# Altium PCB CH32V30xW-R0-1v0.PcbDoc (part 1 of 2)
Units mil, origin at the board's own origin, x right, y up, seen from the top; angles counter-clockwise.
Board outline 3543.31 x 3070.87 mil, 2 copper layers (Top Layer, Bottom Layer); 66 components, 88 nets, 346 pads, 719 vias.
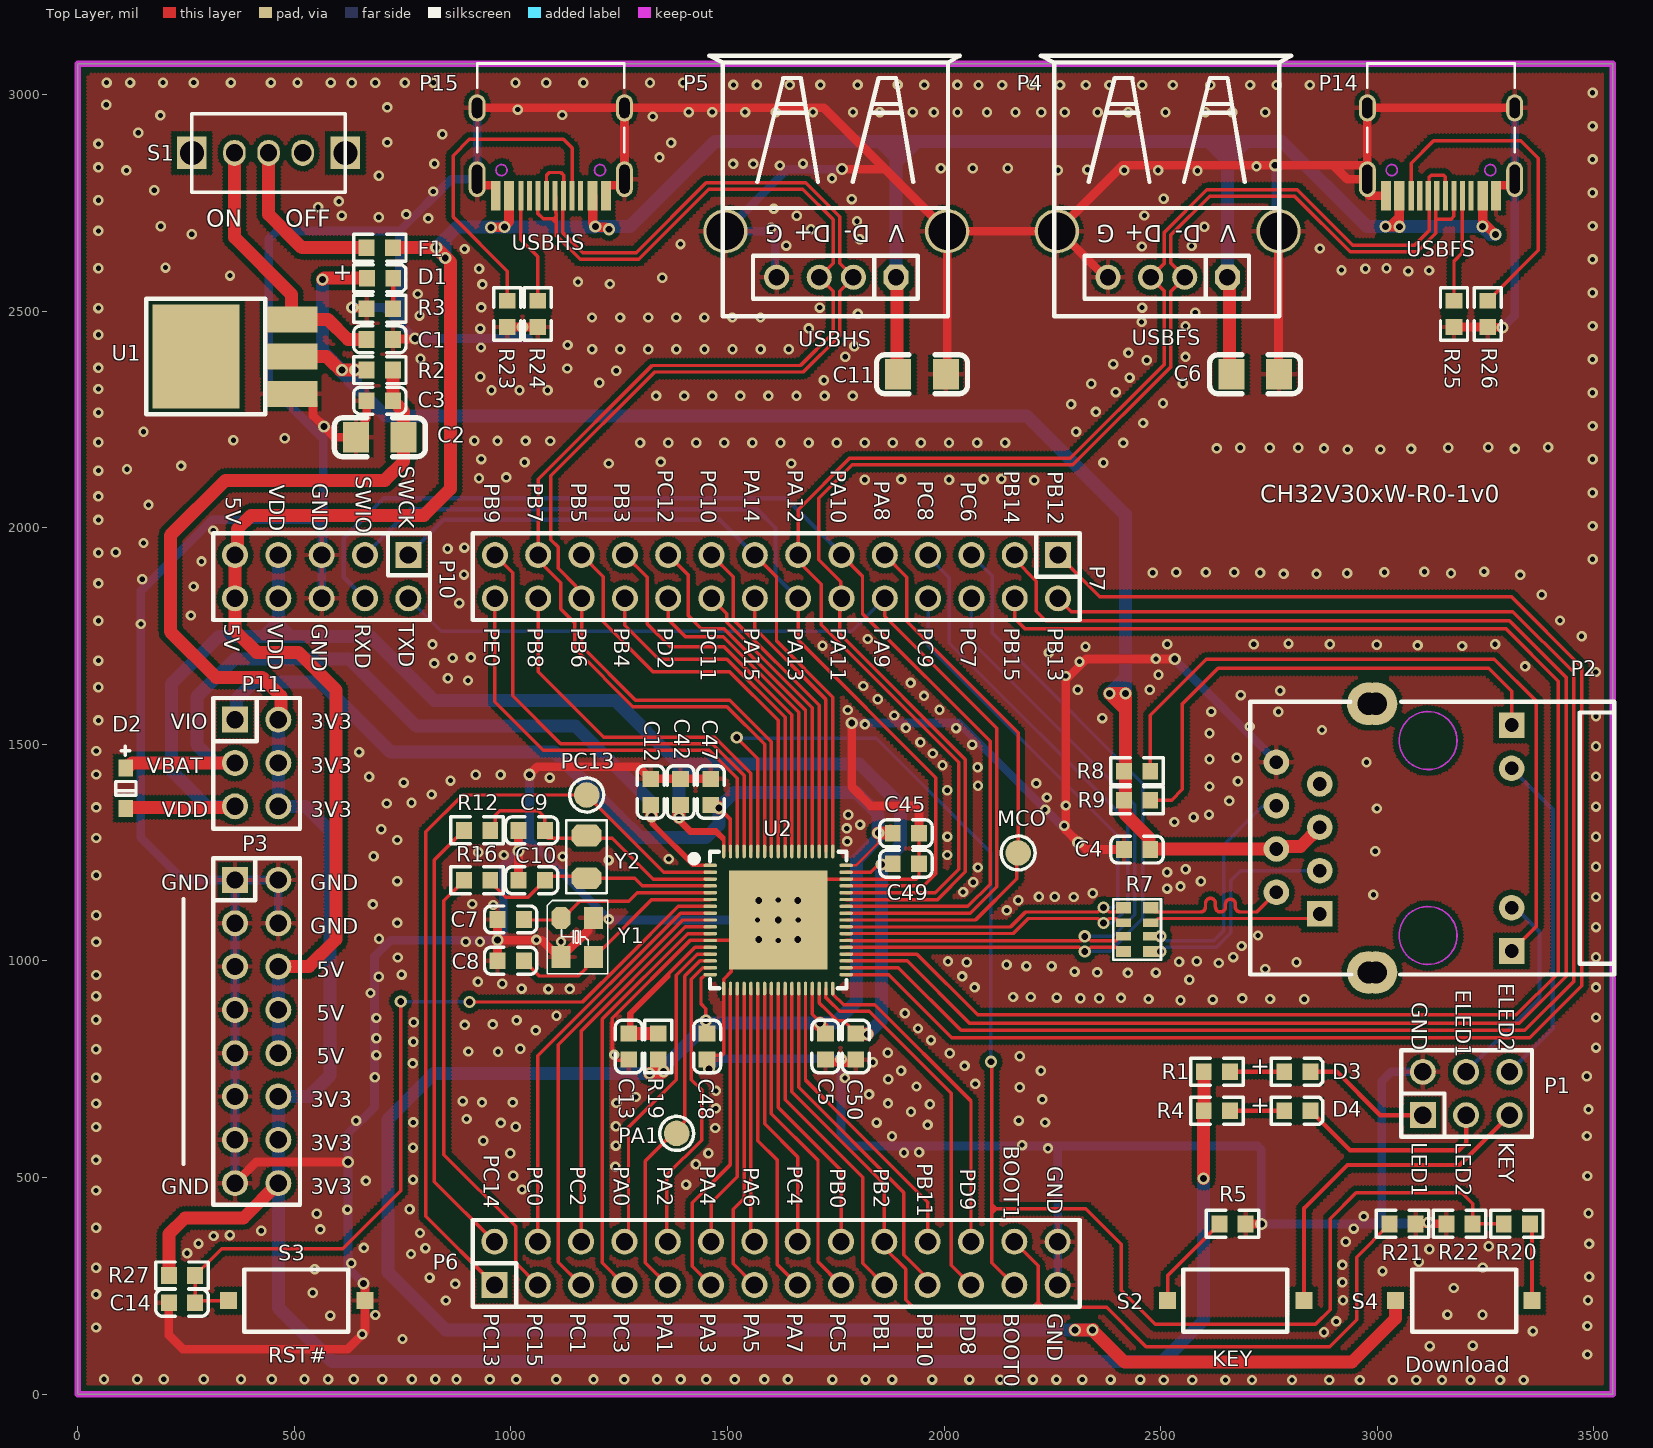
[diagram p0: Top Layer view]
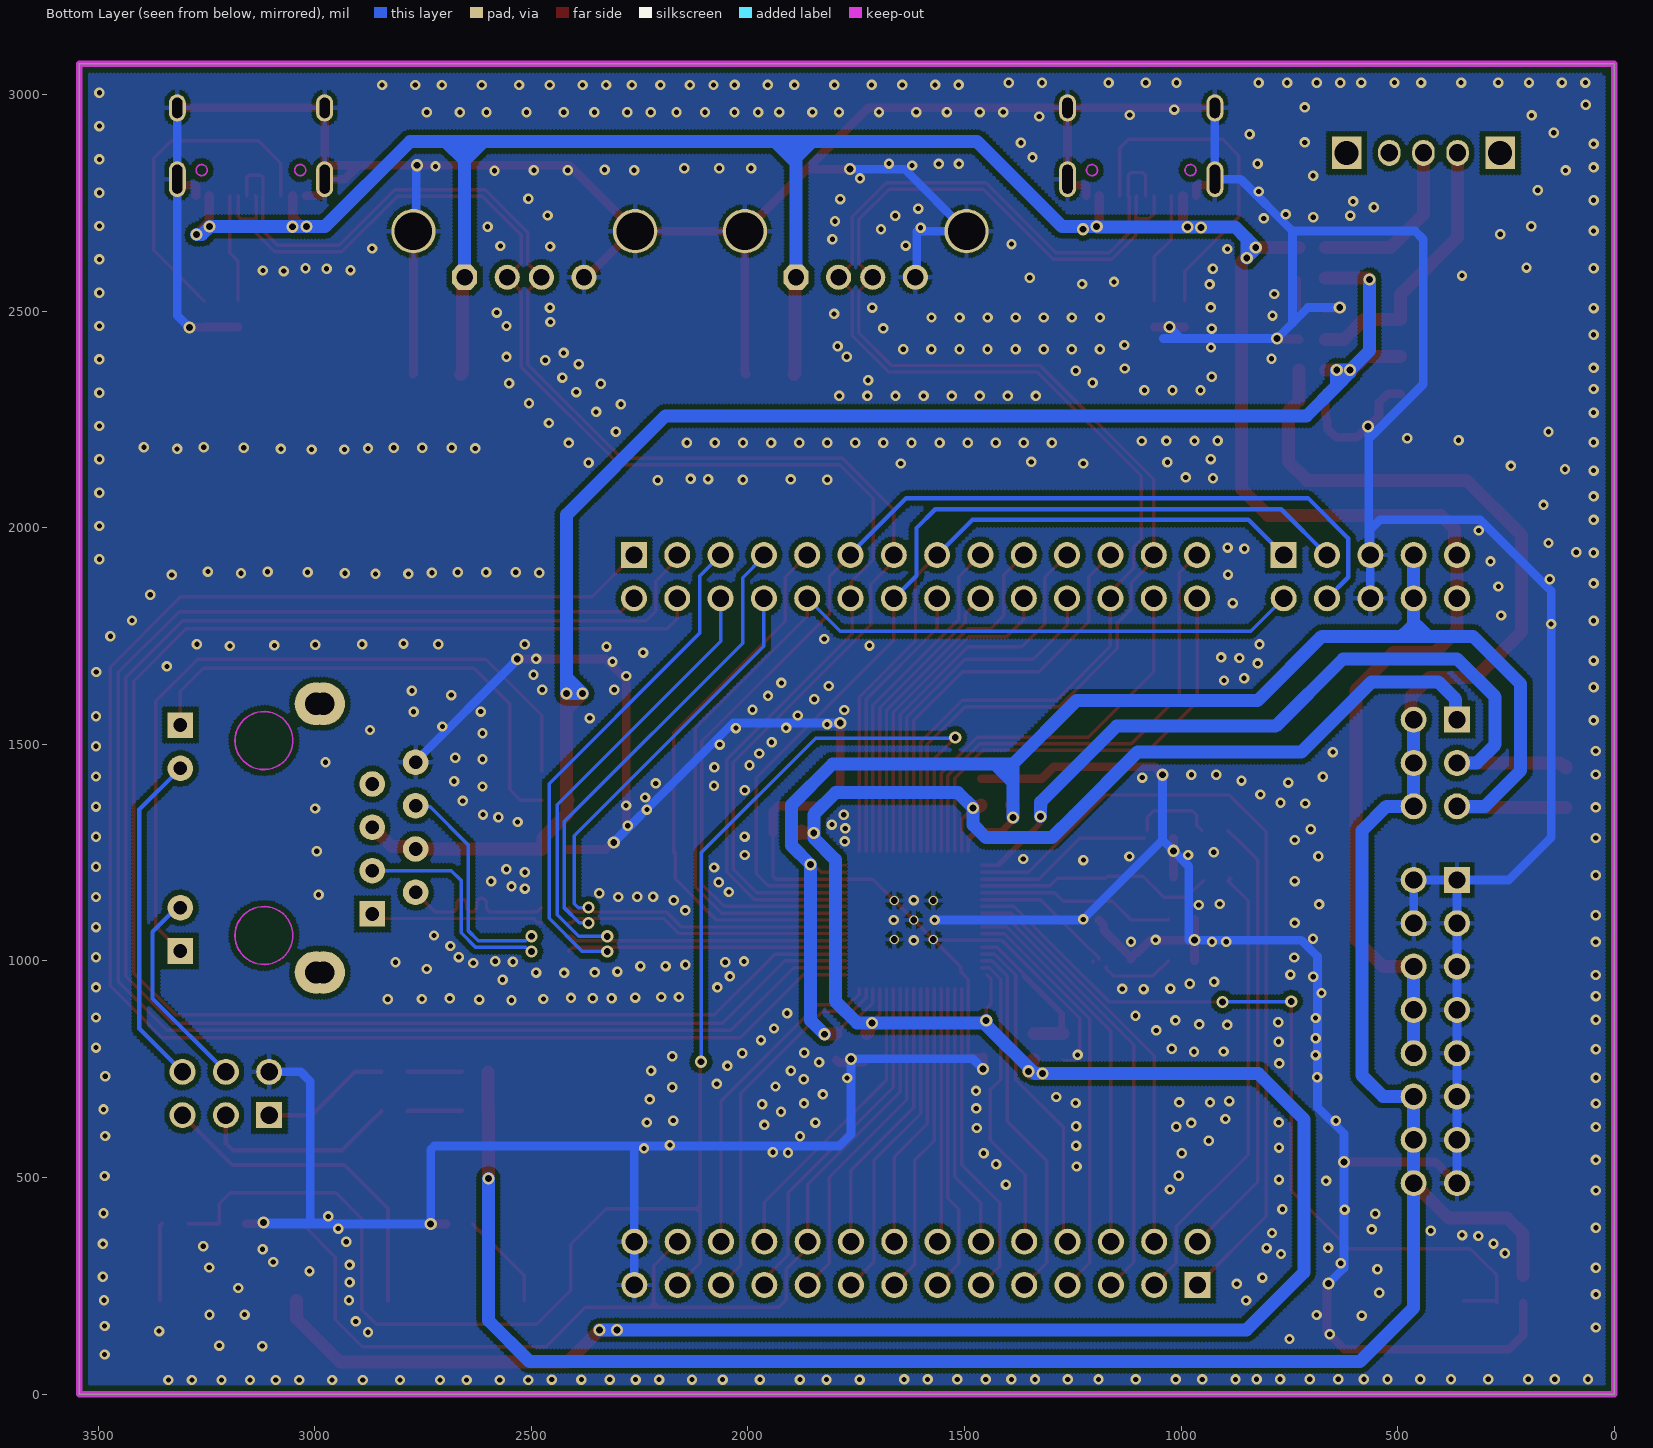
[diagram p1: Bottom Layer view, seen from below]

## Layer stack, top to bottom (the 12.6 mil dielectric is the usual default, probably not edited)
Top Solder: solder mask 0.4, Solder Resist, Dk 3.5
Top Layer: signal copper 1.4
Dielectric 1: dielectric 12.6, FR-4, Dk 4.8
Bottom Layer: signal copper 1.4
Bottom Solder: solder mask 0.4, Solder Resist, Dk 3.5

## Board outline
0,0 3543.31,0 3543.31,3070.87 0,3070.87

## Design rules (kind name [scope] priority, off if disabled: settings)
Clearance Clearance_1 [InPolygon] p1: gap=12 ignorepadtopadclearanceinfootprint=FALSE
Clearance [All] p2: gap=7 ignorepadtopadclearanceinfootprint=FALSE
ComponentClearance [All] p1 off: gap=10 collisioncheckmode=3 verticalgap=10 showdistances=FALSE
DiffPairsRouting [All] p1: maxlimit=10 minlimit=7 mostfreqgap=8 toplayer_minwidth=7 toplayer_maxwidth=15 toplayer_prefwidth=8 bottomlayer_minwidth=7 bottomlayer_maxwidth=15 bottomlayer_prefwidth=8 maxuncoupledlength=500
MinimumSolderMaskSliver [All] p1 off: minsoldermaskwidth=10
PolygonConnect PolygonConnect_1 [IsVia] p1: connectstyle=Direct reliefconductorwidth=10 reliefentries=4 polygonreliefangle="90 Angle" airgapwidth=10
PolygonConnect [All] p2: connectstyle=Relief reliefconductorwidth=10 reliefentries=4 polygonreliefangle="90 Angle" airgapwidth=10
RoutingVias [All] p1: holewidth=16 width=28 viastyle="Through Hole" minholewidth=12 minwidth=24 maxholewidth=28 maxwidth=50
SilkToSilkClearance [All] p1 off: silktosilkclearance=10
SilkToSolderMaskClearance [IsPad] p1 off: minsilkscreentomaskgap=10 clearancetoexposedcopper=TRUE
SolderMaskExpansion [All] p1: expansion=4 istentingtop=FALSE
Width [All] p1: maxlimit=100 minlimit=6 preferedwidth=10
25 further rules are at their usual default settings.

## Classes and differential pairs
differential pair NewDifferentialPair6: +PB7 -PB6
differential pair NewDifferentialPair5: +PA12 -PA11
differential pair NewDifferentialPair4: +ERXN1 -ERXP1
differential pair NewDifferentialPair3: +ETXN1 -ETXP1
differential pair NewDifferentialPair2: +ERXN -ERXP
differential pair NewDifferentialPair1: +ETXN -ETXP

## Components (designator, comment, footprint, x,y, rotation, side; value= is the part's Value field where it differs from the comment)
C1 "0.1uF" 0603_C 667.02,2434.74 r0 top
C2 "10uF" 3216_C 752.33,2208.79 r0 top
C3 "0.1uF" 0603_C 727.65,2293.47 r180 top
C4 "1uF" 0603_C 2415.29,1257.18 r0 top
C5 "0.1uF" 0603_C 1726.06,772.13 r90 top
C6 "10uF" 3216_C 2663,2354.26 r180 top
C7 "22pF" 0603_C 969.2,1095.74 r0 top
C8 "22pF" 0603_C 969.2,1000.46 r0 top
C9 "12pF" 0603_C 1017.69,1301.31 r0 top
C10 "12pF" 0603_C 1017.69,1186.19 r0 top
C11 "10uF" 3216_C 1894,2354.26 r180 top
C12 "0.1uF" 0603_C 1322.64,1420.35 r270 top
C13 "0.1uF" 0603_C 1272.27,832.76 r270 top
C14 "0.1uF" 0603_C 210.37,211 r0 top
C42 "0.1uF" 0603_C 1391.63,1420.35 r270 top
C45 "0.1uF" 0603_C 1881.48,1294.49 r0 top
C47 "0.1uF" 0603_C 1461.63,1359.72 r90 top
C48 "0.1uF" 0603_C 1452.92,832.76 r270 top
C49 "0.1uF" 0603_C 1942.11,1224.49 r180 top
C50 "0.1uF" 0603_C 1796.06,832.76 r270 top
D1 "RED" 0603+ 667.71,2576.01 r0 top
D2 "B0520WS" SOD-323 111,1444.91 r270 top
D3 "BLUE" 0603+ 2785.11,743.99 r0 top
D4 "RED" 0603+ 2785.11,653.99 r0 top
F1 "500mA" 0603 727.65,2646.64 r180 top
MCO "Testpoint" TESTPOINT1 2170.88,1249.31 r0 top
P1 "IO" IDC6-2.54mm 3105.11,643.99 r0 top
P2 "HR911105A" HR911105A 2867.11,1108.49 r90 top
P3 "Ppin" IDC16-2.54mm 363.11,1186.99 r0 top
P4 "USBFS" USBAF 2654,2578.25 r180 top
P5 "USBHS" USBAF 1889,2578.25 r180 top
P6 "HEADER 14x2" IDC28-2.54MM 962.11,251.99 r90 top
P7 "HEADER 14x2" IDC28-2.54MM 2263.11,1936.99 r270 top
P10 "LINK" IDC10-2.54mm 363.11,1936.99 r270 top
P11 "Psel" IDC6-2.54mm 363.11,1556.99 r270 top
P14 "USBFS" TYPE-C-Receptacle-2.0 3147.18,2766.56 r180 top
P15 "USBHS" TYPE-C-Receptacle-2.0 1092.03,2766.56 r180 top
PA1 "Testpoint" TESTPOINT1 1382.65,601.9 r0 top
PC13 "Testpoint" TESTPOINT1 1174.94,1383.09 r0 top
R1 "1K" 0603 2599.48,743.99 r0 top
R2 "0R" 0603 727.65,2364.1 r180 top
R3 "1K" 0603 727.65,2505.37 r180 top
R4 "1K" 0603 2599.48,653.99 r0 top
R5 "10K" 0603 2696,392.95 r180 top
R7 "0Ω" 8P4R-0603 2445.6,1072.43 r270 top
R8 "1K" 0603 2415.29,1437.8 r0 top
R9 "1K" 0603 2415.29,1371.1 r0 top
R12 "NC(0R)" 0603 891.69,1301.31 r0 top
R16 "NC(0R)" 0603 891.69,1186.19 r0 top
R19 "0R" 0603 1339.92,772.13 r90 top
R20 "1K" 0603 3291.86,392.95 r0 top
R21 "10K" 0603 3028,392.95 r0 top
R22 "10K" 0603 3220,392.95 r180 top
R23 "5.1K" 0603 991.75,2523.92 r270 top
R24 "5.1K" 0603 1062.11,2523.92 r270 top
R25 "5.1K" 0603 3177.11,2523.88 r270 top
R26 "5.1K" 0603 3255.21,2523.88 r270 top
R27 "10K" 0603 271,274 r180 top
S1 "SW SPDT" KEY2 440.58,2865.37 r0 top
S2 "KEY" SMD_6.1x3.65x2.5mm-KEY 2830.75,215.99 r180 top
S3 "RST#" SMD_6.1x3.65x2.5mm-KEY 663.07,215.99 r180 top
S4 "Download" SMD_6.1x3.65x2.5mm-KEY 3042,215.99 r0 top
U1 "1117-3.3V" SOT-223 493.11,2309.25 r90 top
U2 "CH32V307W" QFN68_8x8 1617.11,1094.49 r270 top
Y1 "8MHz" XT3225 1115.58,1099.48 r270 top
Y2 "32768Hz" FC-135 1174.48,1289.69 r270 top

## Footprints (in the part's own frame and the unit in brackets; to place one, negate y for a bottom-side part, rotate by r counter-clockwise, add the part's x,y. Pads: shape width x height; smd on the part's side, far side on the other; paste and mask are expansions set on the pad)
8P4R-0603 [mm]
  rect 0.65x0.9 smd: 1(-1.28,-0.8) 4(1.28,-0.8) 5(1.28,0.8) 8(-1.28,0.8)
  rect 0.5x0.9 smd: 2(-0.4,-0.8) 3(0.4,-0.8) 6(0.4,0.8) 7(-0.4,0.8)
  silkscreen extent -1.78,-1.4 1.78,1.4, body extent -1.6,-0.8 1.6,0.8, height 0.6
0603 [mm]
  rect 0.93x0.98 smd: 1(0,0) 2(1.54,0)
  silkscreen extent -0.76,-0.79 2.3,0.79
0603+ [mm]
  rect 0.93x0.98 smd: 1(0,0) 2(1.54,0)
  silkscreen extent -0.76,-0.79 2.27,0.79
0603_C [mm]
  rect 0.93x0.98 smd: 1(0,0) 2(1.54,0)
  silkscreen extent -0.76,-0.79 2.31,0.79
3216_C [mil]
  rect 60x70 smd: 1(0,0) 2(-110,0)
  silkscreen extent -160,-45 50,45
FC-135 [mil]
  oct 50x70 smd: 1(0,0) 2(98.43,0)
  silkscreen extent -35,-47 133,47
HR911105A [mm]
  rect 1.5x1.5 hole 0.8: 1(0,0) 9(-2.175,-11.252) 12(11.075,-11.252)
  round 1.5 hole 0.8: 2(1.27,2.54) 3(2.54,0) 4(3.81,2.54) 5(5.08,0) 6(6.35,2.54) 7(7.62,0) 8(8.89,2.54) 10(0.365,-11.252) 11(8.535,-11.252)
  round 2.5 hole 1.3: ""(-3.43,-2.852) ""(-3.43,-3.3) ""(12.32,-3.3) ""(12.32,-2.852)
  Keep-Out Layer circle w0.1: c10.165,-6.352 r1.7
  Keep-Out Layer circle w0.1: c-1.265,-6.352 r1.7
  silkscreen extent -3.55,-17.27 12.45,4.06
IDC6-2.54mm [mil]
  rect 60x60 hole 40: 1(0,0)
  round 60 hole 40: 2(0,100) 3(100,0) 4(100,100) 5(200,0) 6(200,100)
  silkscreen extent -50,-50 252,150
IDC10-2.54mm [mil]
  rect 60x60 hole 40: 1(0,400)
  round 60 hole 40: 2(100,400) 3(0,300) 4(100,300) 5(0,200) 6(100,200) 7(0,100) 8(100,100) 9(0,0) 10(100,0)
  silkscreen extent -50,-50 150,450
IDC16-2.54mm [mil]
  rect 60x60 hole 40: 1(0,0)
  round 60 hole 40: 2(100,0) 3(0,-100) 4(100,-100) 5(0,-200) 6(100,-200) 7(0,-300) 8(100,-300) 9(0,-400) 10(100,-400) 11(0,-500) 12(100,-500) 13(0,-600) 14(100,-600) 15(0,-700) 16(100,-700)
  silkscreen extent -50,-750 150,50
IDC28-2.54MM [mil]
  rect 60x60 hole 40: 1(0,0)
  round 60 hole 40: 2(100,0) 3(0,-100) 4(100,-100) 5(0,-200) 6(100,-200) 7(0,-300) 8(100,-300) 9(0,-400) 10(100,-400) 11(0,-500) 12(100,-500) 13(0,-600) 14(100,-600) 15(0,-700) 16(100,-700) 17(0,-800) 18(100,-800) 19(0,-900) 20(100,-900) 21(0,-1000) 22(100,-1000) 23(0,-1100) 24(100,-1100) 25(0,-1200) 26(100,-1200) 27(0,-1300) 28(100,-1300)
  silkscreen extent -50,-1351 150,50
KEY2 [mm]
  rect 1.75x1.9 hole 1.4: 0(-4.5,0) 0(4.5,0)
  oval 1.321x1.524 hole 1.016: 1(0,0) 2(-2,0) 3(2,0)
  silkscreen extent -4.51,-2.31 4.5,2.29
QFN68_8x8 [mm]
  round 0.559 hole 0.406: 0(-1.143,1.143) 0(-1.143,-1.143) 0(0,0) 0(1.143,1.143) 0(1.143,-1.143)
  rect 5.8x5.8 smd: 0(0,0)
  oval 0.2x0.8 smd: 1(-3.2,-3.982) 2(-2.8,-3.982) 3(-2.4,-3.982) 4(-2,-3.982) 5(-1.6,-3.982) 6(-1.2,-3.982) 7(-0.8,-3.982) 8(-0.4,-3.982) 9(0,-3.982) 10(0.4,-3.982) 11(0.8,-3.982) 12(1.2,-3.982) 13(1.6,-3.982) 14(2,-3.982) 15(2.4,-3.982) 16(2.8,-3.982) 17(3.2,-3.982) 35(3.2,3.982) 36(2.8,3.982) 37(2.4,3.982) 38(2,3.982) 39(1.6,3.982) 40(1.2,3.982) 41(0.8,3.982) 42(0.4,3.982) 43(0,3.982) 44(-0.4,3.982) 45(-0.8,3.982) 46(-1.2,3.982) 47(-1.6,3.982) 48(-2,3.982) 49(-2.4,3.982) 50(-2.8,3.982) 51(-3.2,3.982)
  oval 0.8x0.2 smd: 18(4.018,-3.2) 19(4.018,-2.8) 20(4.018,-2.4) 21(4.018,-2) 22(4.018,-1.6) 23(4.018,-1.2) 24(4.018,-0.8) 25(4.018,-0.4) 26(4.018,0) 27(4.018,0.4) 28(4.018,0.8) 29(4.018,1.2) 30(4.018,1.6) 31(4.018,2) 32(4.018,2.4) 33(4.018,2.8) 34(4.018,3.2) 52(-4.018,3.2) 53(-4.018,2.8) 54(-4.018,2.4) 55(-4.018,2) 56(-4.018,1.6) 57(-4.018,1.2) 58(-4.018,0.8) 59(-4.018,0.4) 60(-4.018,0) 61(-4.018,-0.4) 62(-4.018,-0.8) 63(-4.018,-1.2) 64(-4.018,-1.6) 65(-4.018,-2) 66(-4.018,-2.4) 67(-4.018,-2.8) 68(-4.018,-3.2)
  silkscreen extent -4,-5.13 4,4
SMD_6.1x3.65x2.5mm-KEY [mm]
  rect 1x1 smd: 1(0,0) 2(8,0)
  silkscreen extent 0.98,-1.83 7.08,1.83
SOD-323 [mm]
  rect 1x0.83 smd: 1(0,0) 2(2.36,0)
  silkscreen extent -1.28,-0.6 1.58,0.6
SOT-223 [mil]
  rect 60x120 smd: 1(0,0) 2(86,0) 3(172,0)
  rect 240x200 smd: ""(86,220)
  silkscreen extent -47,60 219,335
TESTPOINT1 [mm]
  round 1.5 smd: 1(0,0)
  silkscreen extent -1,-1 1,1
TYPE-C-Receptacle-2.0 [mm]
  oval 1x2.1 hole 0.6 slot 1.7 at 90 deg: 0(-4.32,-0.97) 0(4.32,-0.97)
  oval 1x1.6 hole 0.6 slot 1.2 at 90 deg: 0(-4.32,-5.15) 0(4.32,-5.15)
  rect 0.584x1.75 smd: A1(-3.225,0) B1(3.225,0)
  rect 0.6x1.75 smd: A4(-2.45,0) B4(2.45,0)
  rect 0.3x1.75 smd: A5(-1.25,0) A6(-0.25,0) A7(0.25,0) A8(1.25,0) B5(1.75,0) B6(0.75,0) B7(-0.75,0) B8(-1.75,0)
  Keep-Out Layer circle w0.1: c2.89,-1.5 r0.325
  Keep-Out Layer circle w0.1: c-2.89,-1.5 r0.325
  silkscreen extent -4.32,-7.75 4.32,-2.55
USBAF [mm]
  round 2.6 hole 2.2: 0(-3,-2.7) 0(10,-2.7)
  oct 1.473x1.473 hole 0.965: 1(0,0)
  round 1.473 hole 0.965: 2(2.5,0) 3(4.5,0) 4(7,0)
  silkscreen extent -3.75,-12.99 10.95,2.29
XT3225 [mm]
  oct 1.3x1.1 smd: 1(0,0)
  rect 1.3x1.1 smd: 2(2.3,0) 3(2.3,1.9) 4(0,1.9)
  silkscreen extent -1.02,-0.8 3.27,2.74

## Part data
C1 C2 C3 C4 C5 C6 C7 C8 C9 C10 C11 C12 C13 C14 C42 C45 C47 C48 C49 C50: library part CAP, "Capacitor"
D1 D3 D4: library part LED0, "Typical INFRARED GaAs LED"
D2: library part DIODE, "Diode"
F1: library part FUSE1, "Fuse"
MCO PA1 PC13: "测试点"
P1 P11: library part "Header 3X2H", "Header, 3-Pin, Dual row, Right Angle"
P3: library part "Header 8X2H", "Header, 8-Pin, Dual row, Right Angle"
P4 P5: library part USB, "USB Port"
P6 P7: "Header, 14-Pin, Dual row"
P10: library part "Header 5X2H", "Header, 5-Pin, Dual row, Right Angle"
P14 P15: library part TYPE-C1
R1 R2 R3 R4 R5 R8 R9 R12 R16: library part RES
R7: library part R-8P4R, "贴片网络排阻"
R19: library part R
R20 R21 R22 R23 R24 R25 R26 R27: library part Res2, "Resistor"
S2 S3 S4: library part KEY1
U2: "RISC-V FPU HD-MCU, 144MHz, USB_480M, USB OTG, 1000M Ethernet MAC, 2*CAN"
Y1 Y2: library part XTAL, "Crystal Oscillator"

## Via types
v1: diameter 24, hole 12, Top Layer to Bottom Layer, tented both sides, 662 vias
v2: diameter 28, hole 16, Top Layer to Bottom Layer, tented both sides, 57 vias

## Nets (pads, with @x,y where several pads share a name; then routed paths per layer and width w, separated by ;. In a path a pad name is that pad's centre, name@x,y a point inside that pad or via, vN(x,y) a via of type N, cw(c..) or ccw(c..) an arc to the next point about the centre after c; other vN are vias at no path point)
3V3: C2.1 C3.1 P3.12 P3.14 P3.16 P11.2 P11.4 P11.6 R1.1 R2.1 R4.1 R27.2 | length 6141.7
  Top Layer w30: R27.2@210.37,274 210.37,369.46 247.61,406.7 382.82,406.7 P3.16@463.11,486.99 ; P11.2@463.11,1556.99 468.85,1562.73 468.85,1611.71 425.83,1654.72 319.19,1654.72 213.93,1759.98 213.93,1982.33 340.98,2109.39 709.01,2109.39 752.33,2152.71 752.33,2268.78 C3.1@739.15,2281.96 ; C3.1@727.65,2293.47 R2.1@727.65,2364.1 ; v2(2599,498) 2599,653.51 R4.1@2599.48,653.99 R1.1@2599.48,743.99
  Bottom Layer w30: P11.2@463.11,1556.99 P11.4@463.11,1456.99 P11.6@463.11,1356.99 526.07,1356.99 581.87,1301.18 581.87,735.23 533.64,686.99 P3.12@463.11,686.99 P3.14@463.11,586.99 P3.16@463.11,486.99 463.11,199.11 586.51,75.7 2504.71,75.7 2599,170 v2(2599,498)
3V3S: C4.2 D1.1 P2.4 P2.5 R2.2 R8.1 R9.1 U1.2 | length 3960
  Top Layer w30: U1.2@493.11,2395.25 574.64,2395.25 586.53,2383.35 v2@605.78,2364.1 ; v2(565.05,2572.76) 568.29,2576.01 D1.1@667.71,2576.01 ; v2@610.13,2364.1 v2(640.74,2364.1) R2.2@667.02,2364.1 ; P2.5@2867.11,1308.49 2822.67,1264.05 2772.67,1264.05 P2.4@2767.11,1258.49 2766.45,1257.84 2476.58,1257.84 C4.2@2475.92,1257.18 2472.61,1260.48 2472.61,1284.28 2418.05,1338.84 2418.05,1368.34 R9.1@2415.29,1371.1 2418.43,1374.24 2418.43,1580.33 ; 2418.43,1580.33 2381.67,1617.09 v2(2418.43,1617.09) 2418.43,1580.33
  Bottom Layer w30: v2(565.05,2572.76) 565.05,2408.9 v2@609.85,2364.1 ; 660.35,2308.3 640.74,2327.91 ; v2@2381.67,1617.09 v2(2418.43,1617.09) 2418.43,1653.92 ; v2(2381.63,1617.12) 2418.43,1653.92 ; 2418.43,1665.86 2418.43,1653.92 ; v2@609.85,2364.1 v2(640.74,2364.1) 640.74,2327.91 ; v2@609.85,2364.1 v2(610.13,2363.83) 610.13,2358.53 640.74,2327.91 ; 640.74,2327.91 710.58,2258.07 2190.61,2258.07 2418.43,2030.26 2418.43,1653.92
5V: C6.1 C11.1 F1.1 P3.6 P3.8 P3.10 P4.1 P5.1 P10.9 P10.10 P14.A4 P14.B4 P15.A4 P15.B4 | length 7185.9
  Top Layer w22: v2(953.69,2693.18) 954.19,2693.67 984.94,2693.67 v2(985.43,2694.17) 985.43,2695.79 995.57,2705.93 P15.B4@995.57,2766.56 ; P15.A4@1188.48,2766.56 1188.48,2702.96 1194.82,2696.62 v2(1194.82,2695) 1195.97,2693.85 1218.74,2693.85 1223.46,2689.13 v2@1225.08,2689.13 ; P14.B4@3050.73,2766.56 3050.94,2766.34 3050.94,2717.1 ; v2(3051.15,2694.85) v2@3050.94,2695.06 ; v2(3242.64,2695.12) 3243.64,2696.12 v2@3243.64,2705.84 ; P14.A4@3243.64,2766.56 v2@3243.64,2705.84 ; v2(3272.47,2677.01) v2@3243.64,2705.84 ; v2@3050.94,2695.06 3050.74,2695.26 3019.75,2695.26 v2(3019.34,2695.67) 3020.49,2696.82 3030.67,2696.82 3050.94,2717.1 ; v2@3050.94,2695.06 3050.94,2717.1
  Top Layer w30: P3.6@463.11,986.99 533.66,986.99 596.24,1049.56 596.24,1625.97 509.67,1712.54 413.13,1712.54 363.11,1762.57 P10.10@363.11,1836.99 P10.9@363.11,1936.99 368.85,1942.73 368.85,1996.92 400.58,2028.66 799.33,2028.66 860.57,2089.9 860.57,2613.75 v2(827.68,2646.64) F1.1@727.65,2646.64 ; P5.1@1889,2578.25 1891.5,2575.75 1891.5,2356.76 C11.1@1894,2354.26 ; P4.1@2654,2578.25 2658.5,2573.75 2658.5,2358.76 C6.1@2663,2354.26
  Bottom Layer w22: v2@827.68,2645.02 v2(827.68,2646.64) ; v2@847.22,2625.47 847.22,2623.83 v2(848.37,2622.69) ; v2@1194.4,2694.58 v2(1194.82,2695) ; 2654,2887.75 2657.65,2891.4 ; v2(3051.15,2694.85) v2@3051.42,2695.12
  Bottom Layer w30: P3.10@463.11,786.99 P3.8@463.11,886.99 P3.6@463.11,986.99 ; v2@827.68,2645.02 v2@847.22,2625.47 ; v2(827.68,2646.64) 848.37,2667.33 ; v2(848.37,2622.69) 848.37,2667.33 ; 1025.43,2694.17 v2(985.43,2694.17) 875.21,2694.17 848.37,2667.33 ; 1025.43,2694.58 v2@1194.4,2694.58 ; v2(1194.82,2695) 1274.51,2695 1470.92,2891.4 1852.12,2891.4 ; 1867.42,2891.4 1875.56,2891.4 ; P5.1@1889,2578.25 1888.74,2578.51 1888.74,2842.78 ; 2607.05,2891.4 2610.75,2891.4 ; P4.1@2654,2578.25 2654,2848.16 ; 2654,2887.75 2654,2848.16 ; 2654,2891.4 2610.75,2891.4 ; 2657.65,2891.4 2697.24,2891.4 ; 2697.71,2891.4 2697.24,2891.4 ; v2(3051.15,2694.85) 2976.6,2694.85 2780.04,2891.4 2697.24,2891.4 ; v2@3051.42,2695.12 v2(3242.64,2695.12) 3260.74,2677.01 v2(3272.47,2677.01) ; 1852.12,2891.4 1875.56,2891.4 ; 1852.12,2891.4 1888.74,2854.78 ; 1875.56,2891.4 1937.36,2891.4 ; 1875.56,2891.4 1888.74,2878.22 1888.74,2854.78 ; 1888.74,2842.78 1888.74,2854.78 ; 1888.74,2842.78 1937.36,2891.4 ; 1937.36,2891.4 2610.75,2891.4 ; 2610.75,2891.4 2654,2848.16 ; 2654,2848.16 2697.24,2891.4
  other v2: 1226.08,2689.13
BOOT0: P6.25 R20.1 R22.1 U2.63 | length 3691.4
  Top Layer w8: v2(1521.35,1515.67) 1569.86,1467.16 U2.63@1569.86,1252.67 ; v2@2110.39,767.35 2110.39,438.11 2110.39,427.91 ; 2110.46,441.14 2110.46,438.11 2120.65,427.91 ; P6.25@2162.11,251.99 2110.39,303.71 2110.39,417.65 ; R20.1@3291.86,392.95 R22.1@3220,392.95 3220,439.33 3194.71,464.63 2950.92,464.63 2891.27,404.98 2891.27,194.95 2857.35,161.04 2487,161.04 2408.57,239.46 2408.57,346.35 2327.01,427.91 2120.65,427.91 ; 2110.39,417.65 2110.39,427.91 ; 2110.39,417.65 2120.65,427.91 ; 2110.39,427.91 2120.65,427.91
  Bottom Layer w8: v2(1521.35,1515.67) 1522.77,1514.25 1843.55,1514.25 2108.23,1249.56 v2(2108.23,767.35)
BOOT1: P6.20 P6.26 R21.1 U2.28 | length 2400.7
  Top Layer w8: U2.28@1648.6,936.31 1648.6,697.65 1862.11,484.15 1862.11,337.99 1911.35,288.74 1911.35,218.04 1929.15,200.25 2204.74,200.25 ; P6.26@2162.11,351.99 2217.45,296.65 2217.45,211.82 ; 2216.31,211.82 2204.74,200.25 ; 2230.97,200.56 2228.7,200.56 2217.45,211.82 ; R21.1@3028,392.95 3028,391.96 2952.42,316.39 2952.42,171.52 2890.5,109.59 2466.11,109.59 2375.46,200.25 2228.7,200.25 2217.45,200.25 ; 2204.74,200.25 2217.45,200.25 ; 2217.45,200.25 2217.45,211.82
ELED1: P1.4 P2.10 | length 481
  Bottom Layer w10: P1.4@3205.11,743.99 3374.55,913.43 3374.55,1067.28 3318.97,1122.86 P2.10@3310.1,1122.86
ELED2: P1.6 P2.11 | length 781.4
  Bottom Layer w10: P1.6@3305.11,743.99 3405.17,844.06 3405.17,1349.44 P2.11@3310.1,1444.52
ERXN: P7.6 R7.3 U2.40 | length 1664.3
  Top Layer w8: U2.40@1773.89,1047.24 1785.57,1047.24 1785.95,1046.87 v2@2317.7,1046.87 ; v2(2324.72,1056.86) 2328.24,1056.86 2338.24,1046.86 2396.87,1046.86 2400.39,1050.37 2400.39,1050.84 2406.23,1056.68 R7.3@2414.11,1056.68
  Bottom Layer w8: P7.6@2063.11,1836.99 2063.11,1737.7 2439.92,1360.88 2439.92,1106.35 2390.43,1056.86 v2(2324.72,1056.86)
ERXN1: P2.6 R7.6 | length 523.7
  Top Layer w8: v2(2499.37,1056.94) 2505.17,1056.94 v2@2505.75,1056.36
  Bottom Layer w8: v2(2499.37,1056.94) 2502.89,1056.94 2512.89,1046.94 2568.69,1046.94 2568.77,1046.86 2622.68,1046.86 2646.06,1070.24 2646.06,1268.46 2733.09,1355.49 2764.1,1355.49 P2.6@2767.11,1358.49
ERXP: P7.5 R7.4 U2.39 | length 1803.6
  Top Layer w8: U2.39@1773.89,1031.5 1785.57,1031.5 1785.95,1031.87 2311.49,1031.87 ; v2(2324.72,1021.86) 2328.24,1021.86 2338.24,1031.86 2396.87,1031.86 2397.9,1030.83 2405.31,1030.83 R7.4@2414.11,1022.04
  Bottom Layer w8: P7.5@2063.11,1936.99 2111.65,1888.44 2111.65,1756.64 2152.15,1716.14 2458.98,1409.32 2458.98,1098.8 2382.03,1021.86 v2(2324.72,1021.86)
ERXP1: P2.3 R7.5 | length 522.6
  Top Layer w8: v2(2499.37,1021.94) 2505.33,1021.94 v2@2505.75,1022.36
  Bottom Layer w8: v2(2499.37,1021.94) 2502.89,1021.94 2512.89,1031.94 2562.48,1031.94 2562.56,1031.86 2628.89,1031.86 2661.65,1064.62 2661.65,1185.75 2684.4,1208.49 P2.3@2867.11,1208.49
ETXN: P7.8 R7.1 U2.42 | length 1590
  Top Layer w8: U2.42@1773.89,1078.74 1785.57,1078.74 1785.95,1078.37 2153.25,1078.37 2187.88,1113 2354.52,1113 2364.52,1123 v2(2368.03,1123) 2371.55,1123 2381.55,1113 2396.87,1113 2397.9,1114.03 2405.31,1114.03 R7.1@2414.11,1122.82
  Bottom Layer w8: P7.8@1963.11,1836.99 1963.11,1726.66 2400.92,1288.85 2400.92,1132.02 2391.9,1123 v2(2368.03,1123)
ETXN1: P2.2 R7.8 | length 395.9
  Top Layer w8: R7.8@2477.1,1122.82 2485.89,1114.03 2493.3,1114.03 2494.33,1113 2587.97,1113 2591.97,1113 ccw(c2591.97,1124.5) 2603.47,1124.5 2603.47,1133.09 cw(c2614.97,1133.09) 2626.47,1133.09 2626.47,1124.5 ccw(c2637.97,1124.5) 2649.47,1124.5 2649.47,1131.14 cw(c2660.97,1131.14) 2672.47,1131.14 2672.47,1124.5 ccw(c2683.97,1124.5) 2683.97,1113 2703.24,1113 2721.61,1113 P2.2@2767.11,1158.49
ETXP: P7.7 R7.2 U2.41 | length 1742.4
  Top Layer w8: U2.41@1773.89,1062.99 1785.57,1062.99 1785.95,1063.37 2159.46,1063.37 2194.1,1098 2354.52,1098 2364.52,1088 v2(2368.03,1088) 2371.55,1088 2381.55,1098 2396.87,1098 2400.39,1094.49 2400.39,1094.02 2406.23,1088.18 R7.2@2414.11,1088.18
  Bottom Layer w8: P7.7@1963.11,1936.99 1963.11,1933.67 2012.27,1884.5 2012.27,1733.32 2423.46,1322.13 2423.46,1122.16 2389.3,1088 v2(2368.03,1088)
ETXP1: P2.1 R7.7 | length 398.7
  Top Layer w8: R7.7@2477.1,1088.18 2484.97,1088.18 2490.81,1094.02 2490.81,1094.49 2494.33,1098 2856.61,1098 P2.1@2867.11,1108.49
